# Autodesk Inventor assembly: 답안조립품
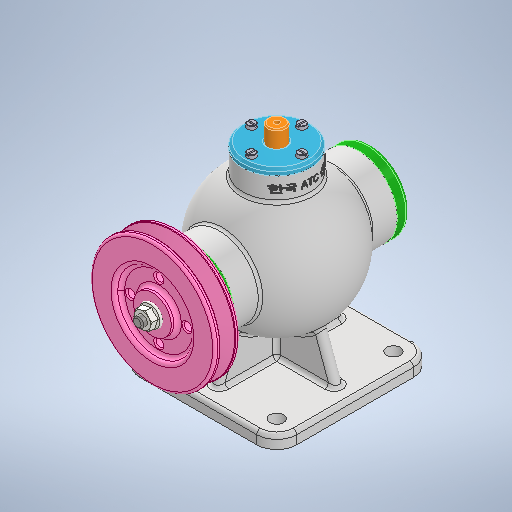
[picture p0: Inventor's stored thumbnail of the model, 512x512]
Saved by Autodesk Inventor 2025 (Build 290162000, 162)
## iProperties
Created: 2024-07
Part Number: 답안조립품
Document SubType Name: Assembly
Designer: deana
Author: deana
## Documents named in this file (15)
- C:\Users\deana\Desktop\740708V1009\답안조립품.iam
- C:\Users\deana\Desktop\740708V1009\본체.ipt
- C:\Users\deana\Desktop\캐드\07.11(목)\20240518\공용부품_20240518_2\뒤커버\뒤커버.ipt
- C:\Users\deana\Desktop\캐드\07.11(목)\20240518\공용부품_20240518_2\앞커버\앞커버.ipt
- C:\Users\deana\Desktop\740708V1009\편심축\편심축.ipt
- C:\Users\deana\Desktop\740708V1009\베어링- 6202\베어링- 6202.ipt
- C:\Users\deana\Desktop\740708V1009\칼라\칼라.ipt
- C:\Users\deana\Desktop\740708V1009\상부커버\상부커버.ipt
- C:\Users\deana\Desktop\740708V1009\키 4 x 4 x 12\키 4 x 4 x 12.ipt
- C:\Users\deana\Desktop\740708V1009\오일실 15 30 7\오일실 15 30 7.ipt
- C:\Users\deana\Desktop\740708V1009\V-벨트풀리\V-벨트풀리.ipt
- C:\Users\deana\Desktop\740708V1009\너트 M8\너트 M8.ipt
- C:\Users\deana\Desktop\740708V1009\볼트 M4 x 16\볼트 M4 x 16.ipt
- C:\Users\deana\Desktop\740708V1009\볼트 M4 x 12\볼트 M4 x 12.ipt
- C:\Users\deana\Desktop\740708V1009\슬라이드\슬라이드.ipt
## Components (1 placed, 1 different names)
1. V-벨트풀리:1 — 각도:7
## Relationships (1: Angle 1)
- 각도:7 [Angle]: V-벨트풀리:1
